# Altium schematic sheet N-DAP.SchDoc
size A4; DocumentNumber: 1; SheetNumber: 1; SheetTotal: 1; PageSetup: Record=PageOptions¦CenterHorizontal=True¦CenterVertical=True¦PrintScale=0.05¦XCorrection=1.00¦YCorrection=1.00¦PrintKind=0¦BorderSize=5000000¦LeftOffset=0¦BottomOffset=0¦Orientation=2¦PaperLength=1000¦PaperWidth=1000¦Scale=100¦PaperSource=7¦PrintQuality=-3¦MediaType=1¦DitherType=10¦PrintScaleMode=1¦PaperKind=12mm¦PaperIndex=126
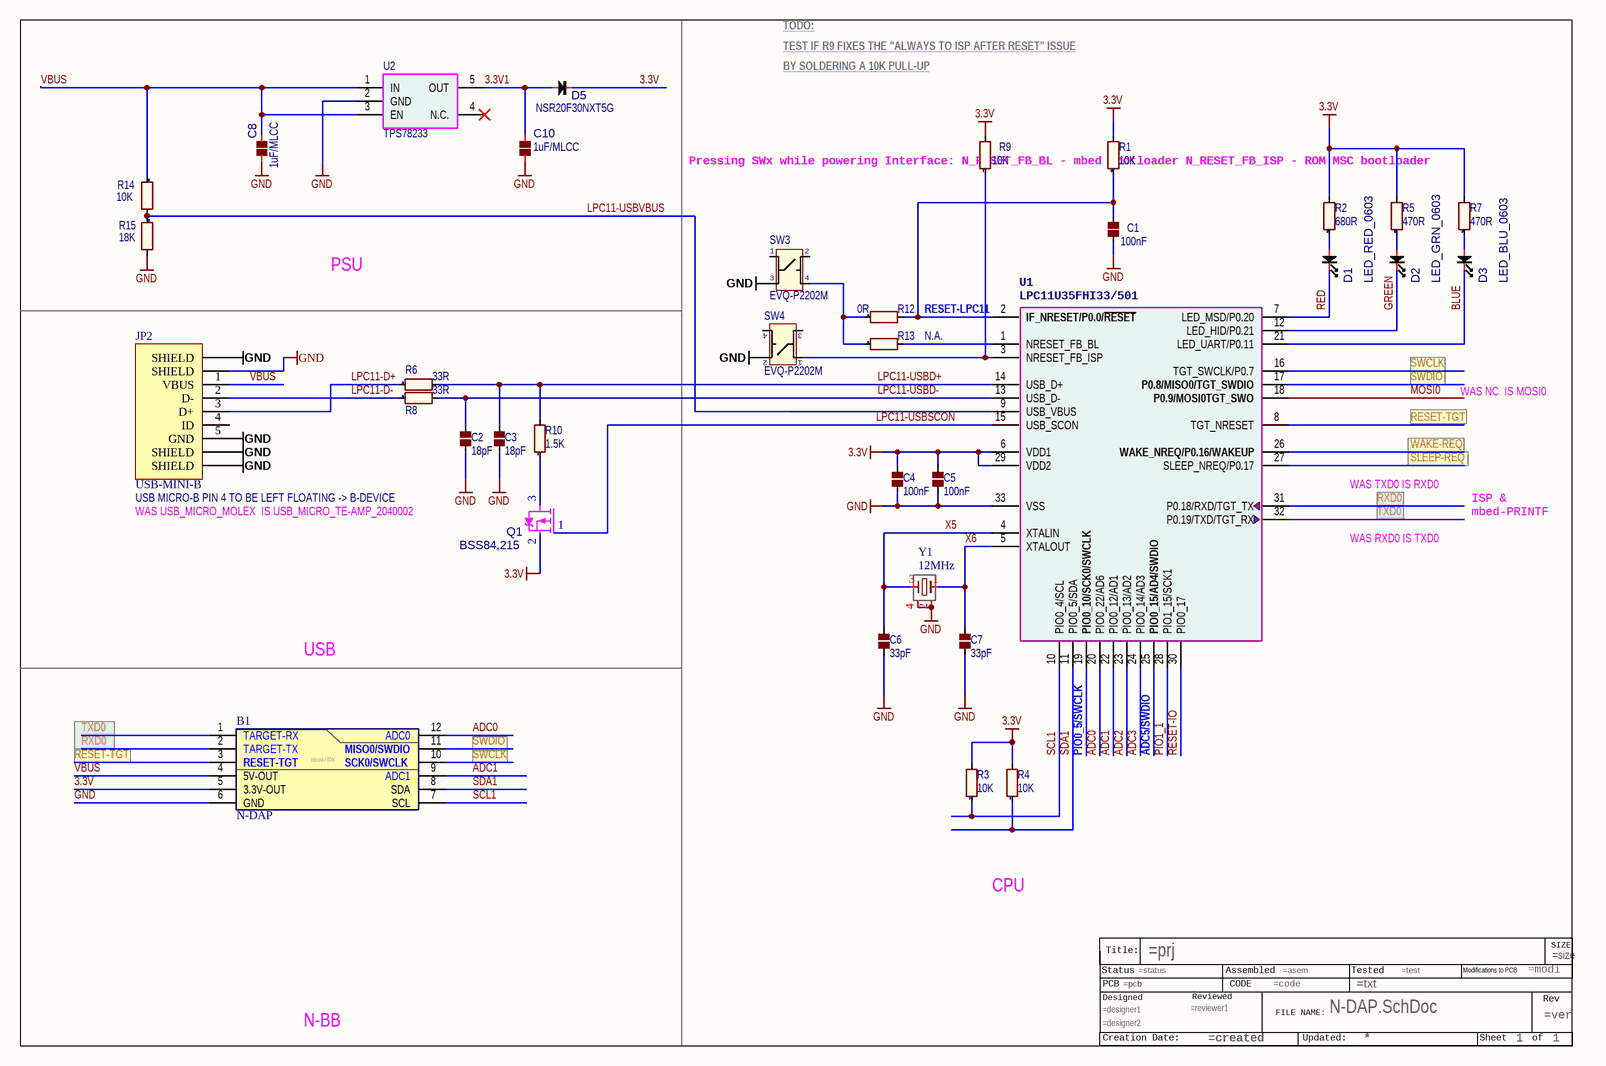
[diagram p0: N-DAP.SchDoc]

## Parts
?*??  FILE_NAME: N-DAP.SchDoc  PAGE NUMPER: 1  (hidden comment: TITLEBLOCK3)  (graphical)
B1  N-DAP  [N-DAP]  (no BOM)
C1  100nF  [0603_cap]
C2  18pF  [0603_cap]
C3  18pF  [0603_cap]
C4  100nF  [0603_cap]
C5  100nF  [0603_cap]
C6  33pF  [0603_cap]
C7  33pF  [0603_cap]
C8  1uF/MLCC  [0603_CAP]
C10  1uF/MLCC  [0603_CAP]
D1  LED_RED_0603  [0603_LED_RED]
D2  LED_GRN_0603  [0603_LED_GRN]
D3  LED_BLU_0603  [0603_LED_BLU]
D5  NSR20F30NXT5G  [0603_DIODE-CDSU101A]
JP2  USB-MINI-B  [USB-MINI-B-HIR-UX60A-MB-5ST]
Q1  BSS84,215  [SOT323/SC70-3_SMALL]
R1  10K  [0603_res]
R2  680R  [0603_res]
R3  10K  [0603_res]
R4  10K  [0603_res]
R5  470R  [0603_res]
R6  33R  [0603_res]
R7  470R  [0603_res]
R8  33R  [0603_res]
R9  10K  [0603_res]
R10  1.5K  [0603_res]
R12  0R  [0603_res]
R13  N.A.  [0603_res]  (no BOM)
R14  10K  [0603_res]
R15  18K  [0603_res]
SW3  EVQ-P2202M  [BUTTON_4.7x3.5mm]
SW4  EVQ-P2202M  [BUTTON_4.7x3.5mm]
U1  LPC11U35FHI33/501  [QFN32_0.5mm_PAD]
U2  TPS78233  [SOT23-5_0.95mm-NOSILK]
Y1  12MHz  [CRY-SMD4-2.5x2mm]

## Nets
3.3V: B1.5(3.3V-OUT) C4.1 C5.1 D5.2 Q1.2(S) R1.2 R2.2 R3.2 R4.2 R5.2 R7.2 R9.2 U1.6(VDD1) U1.29(VDD2)
GND: B1.6(GND) C1.2 C2.2 C3.2 C4.2 C5.2 C6.2 C7.2 C8.1 C10.1 JP2.5(GND) JP2.6(SHIELD) JP2.7(SHIELD) JP2.8(SHIELD) JP2.9(SHIELD) R15.2 SW3.3 SW4.2 U1.33(VSS) U2.2(GND) Y1.2 Y1.4
3.3V1: C10.2 D5.1 U2.5(OUT)
ADC0: B1.12(ADC0) U1.20(PIO0_22/AD6)
ADC1: B1.9(ADC1) U1.22(PIO0_12/AD1)
ADC2: U1.23(PIO0_13/AD2)
ADC3: U1.24(PIO0_14/AD3)
ADC5/SWDIO: U1.25(PIO0_15/AD4/SWDIO)
BLUE: D3.2 U1.21(LED_UART/P0.11)
GREEN: D2.2 U1.12(LED_HID/P0.21)
LPC11-D+: JP2.3(D+) R6.1
LPC11-D-: JP2.2(D-) R8.1
LPC11-USBD+: C3.1 R6.2 R10.2 U1.14(USB_D+)
LPC11-USBD-: C2.1 R8.2 U1.13(USB_D-)
LPC11-USBSCON: Q1.1(G) U1.15(USB_SCON)
LPC11-USBVBUS: R14.2 R15.1 U1.9(USB_VBUS)
MOSI0: U1.18(P0.9/MOSI0TGT_SWO)
PIO0_5/SWCLK: U1.19(PIO0_10/SCK0/SWCLK)
PIO1_1: U1.28(PIO1_15/SCK1)
RED: D1.2 U1.7(LED_MSD/P0.20)
RESET-IO: U1.30(PIO0_17)
RESET-LPC11: C1.1 R1.1 R12.2 U1.2(IF_NRESET/P0.0/~{RESET})
RESET-TGT: B1.3(RESET-TGT) U1.8(TGT_NRESET)
RXD0: B1.2(TARGET-TX) U1.31(P0.18/RXD/TGT_TX)
SCL1: B1.7(SCL) R3.1 U1.10(PIO0_4/SCL)
SDA1: B1.8(SDA) R4.1 U1.11(PIO0_5/SDA)
SLEEP-REQ: U1.27(SLEEP_NREQ/P0.17)
SWCLK: B1.10(SCK0/SWCLK) U1.16(TGT_SWCLK/P0.7)
SWDIO: B1.11(MISO0/SWDIO) U1.17(P0.8/MISO0/TGT_SWDIO)
TXD0: B1.1(TARGET-RX) U1.32(P0.19/TXD/TGT_RX)
VBUS: B1.4(5V-OUT) C8.2 JP2.1(VBUS) R14.1 U2.1(IN) U2.3(EN)
WAKE-REQ: U1.26(WAKE_NREQ/P0.16/WAKEUP)
X5: C6.1 U1.4(XTALIN) Y1.3
X6: C7.1 U1.5(XTALOUT) Y1.1
NetD1_1: D1.1 R2.1
NetD2_1: D2.1 R5.1
NetD3_1: D3.1 R7.1
NetQ1_3: Q1.3(D) R10.1
NetR9_1: R9.1 SW4.1 U1.3(NRESET_FB_ISP)
NetR12_1: R12.1 R13.1 SW3.4
NetR13_2: R13.2 U1.1(NRESET_FB_BL)

Not connected (* = marked no-connect by the designer): ?*?? ?1; JP2 4(ID); SW3 1 2; SW4 3 4; U2 4(N.C.)*

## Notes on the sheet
- TODO:
- TEST IF R9 FIXES THE "ALWAYS TO ISP AFTER RESET" ISSUE
- BY SOLDERING A 10K PULL-UP
- Pressing SWx while powering Interface:
  N_RESET_FB_BL - mbed bootloader
  N_RESET_FB_ISP - ROM MSC bootloader
- PSU
- WAS NC  IS MOSI0
- (near JP2) USB MICRO-B PIN 4 TO BE LEFT FLOATING -> B-DEVICE
- (near JP2) WAS USB_MICRO_MOLEX  IS USB_MICRO_TE-AMP_2040002
- WAS TXD0 IS RXD0
- ISP &
- mbed-PRINTF
- WAS RXD0 IS TXD0
- USB
- CPU
- N-BB

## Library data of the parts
C1 C4 C5 = C: CAPACITOR; Divider: 1; S.Description: Multilayer Ceramic Capacitors MLCC - SMD/SMT 50volts 0.1uF 10% X7R
C2 C3 = C: CAPACITOR; Divider: 1
C6 C7 = C: CAPACITOR; Divider: 1; S.Description: Multilayer Ceramic Capacitors MLCC - SMD/SMT 50volts 33pF 5% C0G
C8 C10 = C: CAPACITOR; Divider: 1; S.Description: Multilayer Ceramic Capacitors MLCC - SMD/SMT 0603 1.0uF 16volts X7R 10%
D1 = LED: Divider: 1
D2 = LED: Divider: 1; S.Description: Standard LEDs - SMD Green, 570nm 10mcd, 2mA
D3 = LED: Divider: 1; S.Description: Standard LEDs - SMD Blue, 470nm 45mcd, 5mA
D5 = DIODE: S.Description: Schottky Diodes & Rectifiers 0603 FC SCHOTTKY DIODES; Divider: 1
JP2 = USB-MINI-B: Divider: 1; S.Description: USB Connectors MINI B RECEPT RA SMT W/O POST
Q1 = mosfet BSS84: POWER MOSFET-P SOT23; S.Description: MOSFET -50V 200mW; Divider: 1
R1 R3 R4 R9 R14 = R: RESISTOR; Divider: 1; S.Description: Thick Film Resistors - SMD 0603 10Kohms 1% Tol
R2 = R: RESISTOR; Divider: 1; S.Description: Thin Film Resistors - SMD 1/16W 680ohm 0.5% 25ppm
R5 R7 = R: RESISTOR; Divider: 1; S.Description: Thick Film Resistors - SMD 0603 470ohms 1% Tol
R6 R8 = R: RESISTOR; Divider: 1; S.Description: Thick Film Resistors - SMD 0603 33.0ohms 1% Tol
R10 = R: RESISTOR; Divider: 1; S.Description: Thick Film Resistors - SMD 0603 1.5Kohms 1% Tol
R12 R13 = R: RESISTOR; Divider: 1; S.Description: Thick Film Resistors - SMD 0603 Zero Ohms
R15 = R: RESISTOR; Divider: 1; S.Description: Thick Film Resistors - SMD 0603 18Kohms 5% Tol
SW3 SW4 = BUTTON_TACT: BUTTON TACTILE; S.Description: Tactile Switches 4.7x3.5mm SMD Light Touch Switch; Divider: 1
U1 = LPC11U35FHI33/501: Divider: 1; S.Description: ARM Microcontrollers - MCU 32-bit ARM Cortex-M0 64KB Flash 12KB SRAM
U2 = NCP702N: Divider: 1; S.Description: LDO Voltage Regulators Sgl Fixed Out LDO 150mA,1uA Quies Crnt
Y1 = XTAL_4PINS: CRYSTAL; S.Description: Crystals 12MHz 30ppm 18pF -20C +70C; Divider: 1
